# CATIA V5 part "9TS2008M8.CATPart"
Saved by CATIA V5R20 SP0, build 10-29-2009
Part number: 9TS2008M8
Revision: ANY
Definition: UNKNOWN
Nomenclature: 9TS2008M8
Source: Unknown
Bounding box of the stored display mesh (mm): x -10 to 10, y -10 to 10, z 0 to 8
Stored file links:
  C:\Users\Utente\Desktop\IO LAVORO\3D X SITO CF\CUMSA\3D files GR\GR 465050-15\9TS2008M8.CATPart
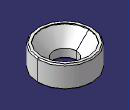
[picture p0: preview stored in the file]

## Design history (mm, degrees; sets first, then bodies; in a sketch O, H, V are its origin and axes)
Body1 "Chaflán1" (main body)
  Solid1: solid without history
